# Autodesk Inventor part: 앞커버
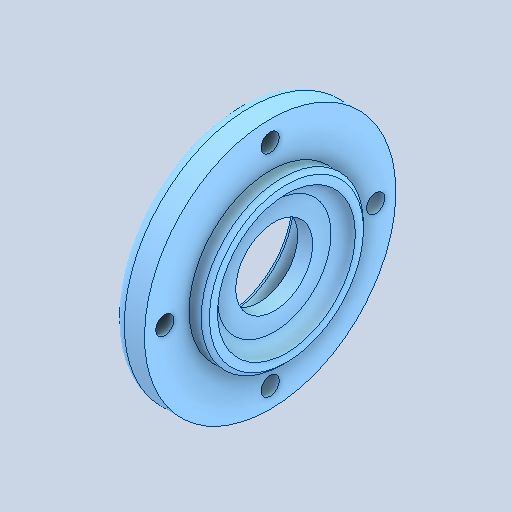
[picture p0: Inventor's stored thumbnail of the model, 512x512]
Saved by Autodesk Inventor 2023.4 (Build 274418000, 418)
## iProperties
Created: 2024-09
Part Number: 앞커버
Material: 알루미늄 6061
Document SubType Name: Modeling
Designer: EDU
Density: 2.7 g/cm^3
Appearance: 기본값
Author: jhkim
Sending System: Autodesk Inventor 2025
Preprocessor: ST-DEVELOPER v20
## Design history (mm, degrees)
feature "솔리드1"
node "솔리드2"
